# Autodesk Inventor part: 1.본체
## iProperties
Created: 2014-11
Part Number: 1.본체
Document SubType Name: Modeling
Designer: tw_037
Density: 2.71 g/cm^3
Material: 알루미늄-6061
Mass: 2777.11 g
Surface Area: 2004.76 cm^2
Volume: 1024.76 cm^3
Author: tw_037
